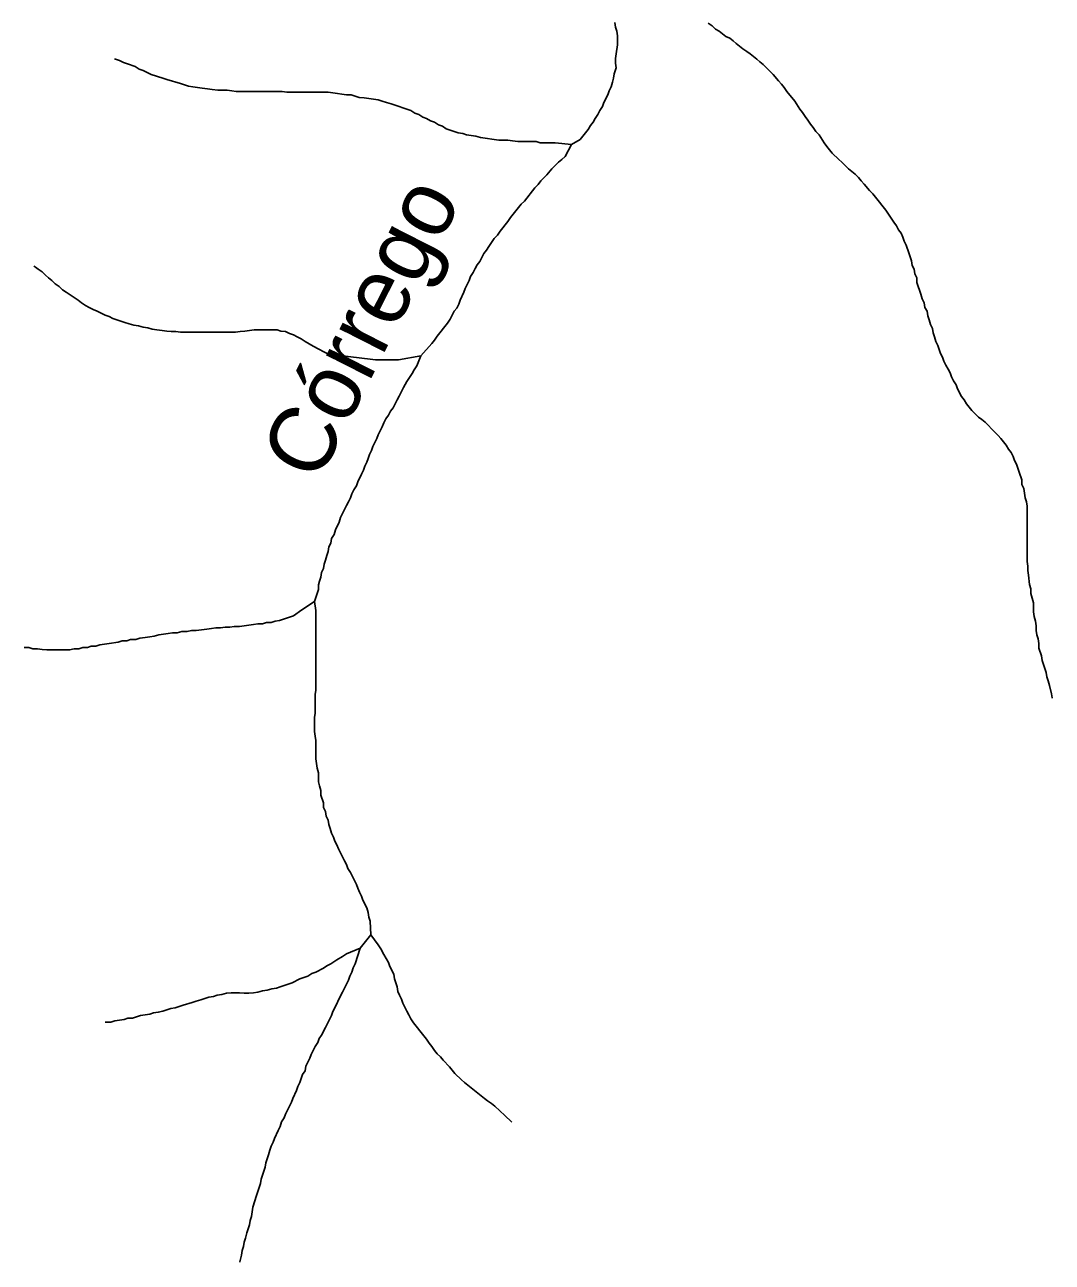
# Model space of a CAD drawing. Extents: x 652.3 to 678, y 7316.9 to 7344.9.
# Drawn here: x 674.888 to 676.134, y 7341.775 to 7343.275 of the extents above; entities that cross this region are included whole.
import ezdxf
from ezdxf.enums import TextEntityAlignment as Align

# ---------------------------------------------------------------- set-up
doc = ezdxf.new("R2010")
doc.units = 0
doc.header["$LTSCALE"] = 0.032
doc.layers.add('61', color=7, linetype='Continuous')
doc.layers.add('7', color=7, linetype='Continuous', lineweight=25)

msp = doc.modelspace()

# ---------------------------------------------------------------- linework, layer by layer
at = {"layer": '7'}
msp.add_line((675.3074, 7342.1721), (675.2947, 7342.1562), dxfattribs=at)
for points in [[(675.6034, 7343.2782), (675.6042, 7343.2726), (675.6058, 7343.2678), (675.6066, 7343.2622), (675.6066, 7343.2511), (675.605, 7343.24), (675.6042, 7343.2344), (675.6042, 7343.2288), (675.605, 7343.2233), (675.6026, 7343.2161), (675.6018, 7343.2105), (675.6003, 7343.2057), (675.5987, 7343.2002), (675.5963, 7343.1954), (675.5947, 7343.1906), (675.5899, 7343.1811), (675.5883, 7343.1763), (675.5851, 7343.1715), (675.5827, 7343.1668), (675.5796, 7343.162), (675.5772, 7343.1572), (675.574, 7343.1532), (675.5708, 7343.1485), (675.5644, 7343.1405), (675.5613, 7343.1365), (675.5509, 7343.1302)], [(675.7164, 7343.2774), (675.7212, 7343.2742), (675.7252, 7343.2702), (675.7299, 7343.2678), (675.7339, 7343.2646), (675.7379, 7343.2614), (675.7427, 7343.2591), (675.7467, 7343.2559), (675.7506, 7343.2527), (675.7546, 7343.2495), (675.7586, 7343.2463), (675.7634, 7343.2431), (675.7673, 7343.24), (675.7713, 7343.2368), (675.7753, 7343.2336), (675.7793, 7343.2304), (675.7833, 7343.2272), (675.7872, 7343.2233), (675.7912, 7343.2193), (675.7952, 7343.2153), (675.8016, 7343.2073), (675.8055, 7343.2034), (675.8087, 7343.1994), (675.8119, 7343.1946), (675.8215, 7343.1827), (675.8278, 7343.1731), (675.831, 7343.1691), (675.8342, 7343.1644), (675.8374, 7343.1596), (675.8405, 7343.1548), (675.8437, 7343.1508), (675.8469, 7343.1461), (675.8509, 7343.1421), (675.8573, 7343.1325), (675.8604, 7343.1278), (675.8636, 7343.1238), (675.8668, 7343.1198), (675.8748, 7343.1119), (675.8787, 7343.1087), (675.8827, 7343.1047), (675.8867, 7343.1007), (675.8907, 7343.0975), (675.8947, 7343.0944), (675.8986, 7343.0904), (675.9018, 7343.0864), (675.9058, 7343.0824), (675.9122, 7343.0745), (675.9161, 7343.0705), (675.9193, 7343.0665)], [(674.9965, 7343.2341), (675.0003, 7343.2328), (675.0027, 7343.232), (675.0075, 7343.2296), (675.0122, 7343.228), (675.0218, 7343.2248), (675.0266, 7343.2217), (675.0313, 7343.2201), (675.0409, 7343.2153), (675.0552, 7343.2105), (675.06, 7343.2089), (675.0767, 7343.2042), (675.0815, 7343.2026), (675.0862, 7343.201), (675.0918, 7343.2002), (675.0974, 7343.1994), (675.1029, 7343.1986), (675.1093, 7343.1978), (675.1149, 7343.197), (675.122, 7343.1962), (675.1332, 7343.1962), (675.1388, 7343.1954), (675.1443, 7343.1946), (675.2, 7343.1946), (675.2056, 7343.1938), (675.2557, 7343.1938), (675.2613, 7343.193), (675.2669, 7343.1922), (675.2724, 7343.1914), (675.278, 7343.1906), (675.2836, 7343.1906), (675.2883, 7343.189), (675.2931, 7343.1874), (675.2995, 7343.1867), (675.3051, 7343.1859), (675.3106, 7343.1851), (675.3162, 7343.1843), (675.321, 7343.1827), (675.3265, 7343.1811), (675.3321, 7343.1795), (675.3417, 7343.1763), (675.3464, 7343.1747), (675.356, 7343.1715), (675.3607, 7343.1684), (675.3655, 7343.1668), (675.3703, 7343.1636), (675.3751, 7343.162), (675.3798, 7343.1588), (675.3846, 7343.1572), (675.3894, 7343.154), (675.3942, 7343.1524), (675.3989, 7343.1493), (675.4133, 7343.1445), (675.4188, 7343.1437), (675.4236, 7343.1421), (675.4292, 7343.1413), (675.4347, 7343.1405), (675.4403, 7343.1389), (675.4459, 7343.1381), (675.457, 7343.1365), (675.4626, 7343.1357), (675.4737, 7343.1357), (675.4793, 7343.1349), (675.4857, 7343.1341), (675.508, 7343.1341), (675.5127, 7343.1325), (675.531, 7343.1325), (675.5509, 7343.1302)], [(675.5509, 7343.1302), (675.543, 7343.1158), (675.539, 7343.1119), (675.535, 7343.1087), (675.531, 7343.1047), (675.527, 7343.1007), (675.5207, 7343.0936), (675.5135, 7343.0864), (675.5103, 7343.0816), (675.5064, 7343.0776), (675.4936, 7343.0617), (675.4897, 7343.0578), (675.4865, 7343.0538), (675.4769, 7343.0418), (675.4737, 7343.0371), (675.4642, 7343.0251), (675.461, 7343.0204), (675.457, 7343.0164), (675.4538, 7343.0116), (675.4507, 7343.0068), (675.4475, 7343.0021), (675.4443, 7342.9981), (675.4395, 7342.9885), (675.4363, 7342.9845), (675.434, 7342.9798), (675.4316, 7342.975), (675.4284, 7342.9702), (675.4268, 7342.9655), (675.4244, 7342.9607), (675.422, 7342.9559), (675.4204, 7342.9511), (675.4157, 7342.9416), (675.4141, 7342.9368), (675.4117, 7342.932), (675.4085, 7342.9281), (675.4037, 7342.9185), (675.4005, 7342.9137), (675.3878, 7342.8978), (675.3846, 7342.893), (675.3814, 7342.8891), (675.3679, 7342.8739)], [(675.9193, 7343.0665), (675.9321, 7343.0506), (675.9384, 7343.041), (675.9416, 7343.0363), (675.9448, 7343.0315), (675.9472, 7343.0267), (675.9504, 7343.0227), (675.9527, 7343.018), (675.9543, 7343.0132), (675.9567, 7343.0084), (675.9599, 7342.9989), (675.9615, 7342.9941), (675.9631, 7342.9893), (675.9639, 7342.9838), (675.9663, 7342.979), (675.9671, 7342.9734), (675.9695, 7342.9686), (675.9695, 7342.9631), (675.971, 7342.9583), (675.9726, 7342.9535), (675.9742, 7342.9487), (675.9758, 7342.9432), (675.9782, 7342.9384), (675.979, 7342.9328), (675.9822, 7342.9281), (675.983, 7342.9225), (675.9846, 7342.9177), (675.9862, 7342.9121), (675.9885, 7342.9074), (675.9893, 7342.9018), (675.9909, 7342.897), (675.9925, 7342.8915), (675.9949, 7342.8867), (675.9965, 7342.8819), (675.9981, 7342.8771), (676.0005, 7342.8724), (676.0021, 7342.8676), (676.0045, 7342.8628), (676.0076, 7342.858), (676.01, 7342.8533), (676.0116, 7342.8485), (676.014, 7342.8437), (676.0172, 7342.8389), (676.0188, 7342.8342), (676.0236, 7342.8246), (676.0267, 7342.8206), (676.0299, 7342.8159), (676.0331, 7342.8119), (676.0363, 7342.8079), (676.0442, 7342.7999), (676.0482, 7342.7968), (676.0522, 7342.7936), (676.0562, 7342.7896), (676.0602, 7342.7856), (676.0641, 7342.7816), (676.0681, 7342.7777), (676.0713, 7342.7737), (676.0777, 7342.7657), (676.0808, 7342.761), (676.084, 7342.757), (676.0864, 7342.7522), (676.088, 7342.7474), (676.0904, 7342.7427), (676.092, 7342.7379), (676.0936, 7342.7331), (676.0968, 7342.7236), (676.0968, 7342.718), (676.0991, 7342.7132), (676.0999, 7342.7076), (676.1007, 7342.7021), (676.1023, 7342.6973), (676.1031, 7342.6917), (676.1031, 7342.6249), (676.1039, 7342.6193), (676.1039, 7342.6138), (676.1047, 7342.6082), (676.1063, 7342.597), (676.1079, 7342.5915), (676.1079, 7342.5859), (676.1095, 7342.5803), (676.1111, 7342.5748), (676.1111, 7342.5636), (676.1119, 7342.5581), (676.1135, 7342.5525), (676.1143, 7342.5469), (676.1143, 7342.5413), (676.1151, 7342.5358), (676.1167, 7342.531), (676.1174, 7342.5254), (676.1174, 7342.5199), (676.1206, 7342.5103), (676.1214, 7342.5047), (676.123, 7342.5), (676.1246, 7342.4952), (676.1262, 7342.4904), (676.127, 7342.4849), (676.1286, 7342.4801), (676.1302, 7342.4745), (676.1326, 7342.4642), (676.1336, 7342.4595), (676.1337, 7342.4591)], [(674.8989, 7342.9828), (674.8996, 7342.9823), (674.9008, 7342.9814), (674.904, 7342.979), (674.9088, 7342.9758), (674.9128, 7342.9718), (674.9168, 7342.9686), (674.9207, 7342.9655), (674.9247, 7342.9615), (674.9295, 7342.9583), (674.9335, 7342.9543), (674.9382, 7342.9511), (674.943, 7342.9479), (674.9478, 7342.9448), (674.9526, 7342.9416), (674.9565, 7342.9384), (674.9613, 7342.9352), (674.9661, 7342.9328), (674.9709, 7342.9304), (674.9756, 7342.9281), (674.9804, 7342.9257), (674.9852, 7342.9233), (674.99, 7342.9217), (674.9947, 7342.9193), (674.9995, 7342.9177), (675.0043, 7342.9161), (675.0091, 7342.9145), (675.0146, 7342.9129), (675.0202, 7342.9113), (675.0258, 7342.9105), (675.0313, 7342.909), (675.0369, 7342.9082), (675.0425, 7342.9066), (675.048, 7342.9058), (675.0544, 7342.905), (675.06, 7342.9042), (675.0655, 7342.9034), (675.0711, 7342.9034), (675.0767, 7342.9026), (675.0823, 7342.9026), (675.0878, 7342.9026), (675.0934, 7342.9026), (675.099, 7342.9026), (675.1045, 7342.9026), (675.1101, 7342.9026), (675.1157, 7342.9026), (675.1212, 7342.9026), (675.1268, 7342.9026), (675.1324, 7342.9026), (675.138, 7342.9026), (675.1435, 7342.9026), (675.1491, 7342.9034), (675.1547, 7342.9042), (675.1602, 7342.905), (675.1658, 7342.9058), (675.1714, 7342.9058), (675.1769, 7342.9058), (675.1825, 7342.9058), (675.1881, 7342.9058), (675.1937, 7342.9058), (675.1984, 7342.9042), (675.204, 7342.9034), (675.2088, 7342.901), (675.2135, 7342.8994), (675.2183, 7342.897), (675.2231, 7342.8946), (675.2279, 7342.8915), (675.2374, 7342.8859), (675.2573, 7342.8755), (675.2565, 7342.8763), (675.3066, 7342.87), (675.313, 7342.8692), (675.3409, 7342.8692), (675.3679, 7342.8739)], [(675.3679, 7342.8739), (675.3631, 7342.862), (675.36, 7342.8572), (675.3576, 7342.8525), (675.3544, 7342.8477), (675.3512, 7342.8429), (675.3472, 7342.8358), (675.3417, 7342.8254), (675.3393, 7342.8206), (675.3369, 7342.8159), (675.3345, 7342.8111), (675.3313, 7342.8071), (675.3289, 7342.8023), (675.3257, 7342.7976), (675.3234, 7342.7928), (675.321, 7342.788), (675.3162, 7342.7785), (675.3146, 7342.7737), (675.3122, 7342.7689), (675.3098, 7342.7641), (675.3082, 7342.7594), (675.3058, 7342.7546), (675.3043, 7342.7498), (675.3027, 7342.745), (675.3003, 7342.7403), (675.2987, 7342.7355), (675.2963, 7342.7307), (675.2915, 7342.7212), (675.2899, 7342.7164), (675.2867, 7342.7116), (675.2844, 7342.7069), (675.2828, 7342.7021), (675.2804, 7342.6973), (675.278, 7342.6925), (675.2708, 7342.6782), (675.2692, 7342.6726), (675.2645, 7342.6631), (675.2629, 7342.6575), (675.2597, 7342.6527), (675.2589, 7342.6472), (675.2565, 7342.6424), (675.2557, 7342.6368), (675.2541, 7342.6321), (675.2525, 7342.6265), (675.2509, 7342.6217), (675.2501, 7342.6161), (675.2478, 7342.6114), (675.247, 7342.6058), (675.2454, 7342.601), (675.2438, 7342.5963), (675.2438, 7342.5907), (675.239, 7342.5764)], [(674.8873, 7342.5207), (674.8929, 7342.5207), (674.8977, 7342.5191), (674.9032, 7342.5191), (674.9088, 7342.5183), (674.9144, 7342.5175), (674.9422, 7342.5175), (674.9478, 7342.5191), (674.9534, 7342.5191), (674.9581, 7342.5207), (674.9637, 7342.5207), (674.9685, 7342.5223), (674.974, 7342.5223), (674.9788, 7342.5238), (674.9844, 7342.5246), (674.99, 7342.5254), (675.0011, 7342.527), (675.0059, 7342.5286), (675.0114, 7342.5286), (675.0162, 7342.5302), (675.0226, 7342.5302), (675.0274, 7342.5318), (675.0337, 7342.5326), (675.0393, 7342.5334), (675.0449, 7342.5342), (675.0504, 7342.5358), (675.0616, 7342.5374), (675.0671, 7342.5382), (675.0727, 7342.5382), (675.0783, 7342.5398), (675.0846, 7342.5398), (675.0902, 7342.5413), (675.0958, 7342.5413), (675.1021, 7342.5421), (675.1085, 7342.5429), (675.1141, 7342.5437), (675.1197, 7342.5445), (675.1252, 7342.5445), (675.1308, 7342.5453), (675.1364, 7342.5453), (675.1419, 7342.5461), (675.1483, 7342.5461), (675.1539, 7342.5469), (675.1594, 7342.5477), (675.165, 7342.5485), (675.1706, 7342.5493), (675.1761, 7342.5493), (675.1809, 7342.5509), (675.1865, 7342.5509), (675.1913, 7342.5525), (675.1968, 7342.5533), (675.2016, 7342.5549), (675.2064, 7342.5565), (675.2135, 7342.5589), (675.2239, 7342.566), (675.239, 7342.5764)], [(675.239, 7342.5764), (675.2406, 7342.5652), (675.2406, 7342.4689), (675.2398, 7342.4634), (675.2398, 7342.4411), (675.239, 7342.4355), (675.239, 7342.4188), (675.2398, 7342.4132), (675.2406, 7342.4077), (675.2406, 7342.3854), (675.2422, 7342.3743), (675.2438, 7342.3687), (675.2438, 7342.3575), (675.2454, 7342.3528), (675.247, 7342.3472), (675.247, 7342.3416), (675.2501, 7342.3321), (675.2501, 7342.3265), (675.2525, 7342.3217), (675.2533, 7342.3162), (675.2557, 7342.3114), (675.2565, 7342.3058), (675.2581, 7342.3011), (675.2597, 7342.2955), (675.2621, 7342.2907), (675.2637, 7342.2859), (675.2661, 7342.2812), (675.2684, 7342.2764), (675.2756, 7342.2621), (675.278, 7342.2573), (675.2796, 7342.2525), (675.2828, 7342.2477), (675.2852, 7342.243), (675.2875, 7342.2382), (675.2899, 7342.2334), (675.2915, 7342.2286), (675.2939, 7342.2239), (675.2963, 7342.2191), (675.2979, 7342.2143), (675.3027, 7342.2048), (675.3043, 7342.1992), (675.3051, 7342.1936), (675.3066, 7342.1889), (675.3074, 7342.1721)], [(675.3074, 7342.1721), (675.3162, 7342.1602), (675.3194, 7342.1554), (675.3234, 7342.1483), (675.3289, 7342.1387), (675.3305, 7342.134), (675.3353, 7342.1244), (675.3361, 7342.1188), (675.3393, 7342.1093), (675.3401, 7342.1037), (675.3424, 7342.0989), (675.3448, 7342.0942), (675.3464, 7342.0894), (675.3512, 7342.0798), (675.3536, 7342.0751), (675.356, 7342.0703), (675.3592, 7342.0655), (675.3719, 7342.0496), (675.3751, 7342.0456), (675.3783, 7342.0409), (675.3814, 7342.0369), (675.3846, 7342.0321), (675.3878, 7342.0281), (675.3918, 7342.0242), (675.395, 7342.0202), (675.4029, 7342.0122), (675.4093, 7342.0043), (675.4172, 7341.9963), (675.4212, 7341.9931), (675.4252, 7341.9899), (675.4292, 7341.9868), (675.4332, 7341.9836), (675.4371, 7341.9804), (675.4411, 7341.9772), (675.4451, 7341.974), (675.4491, 7341.9708), (675.4538, 7341.9677), (675.4578, 7341.9645), (675.4698, 7341.9533), (675.4779, 7341.9457), (675.4785, 7341.9452)], [(674.9852, 7342.0663), (674.9923, 7342.0663), (674.9971, 7342.0679), (675.0027, 7342.0687), (675.0083, 7342.0695), (675.013, 7342.0711), (675.0186, 7342.0711), (675.0234, 7342.0727), (675.0282, 7342.0743), (675.0337, 7342.0751), (675.0393, 7342.0759), (675.0441, 7342.0775), (675.0496, 7342.0783), (675.0552, 7342.0798), (675.06, 7342.0814), (675.0648, 7342.083), (675.0703, 7342.0838), (675.0751, 7342.0854), (675.0799, 7342.087), (675.091, 7342.0902), (675.0958, 7342.0918), (675.1014, 7342.0934), (675.1109, 7342.0966), (675.1165, 7342.0974), (675.1212, 7342.0989), (675.1268, 7342.0997), (675.1324, 7342.1013), (675.138, 7342.1021), (675.1483, 7342.1021), (675.1539, 7342.1013), (675.1594, 7342.1013), (675.165, 7342.1021), (675.1706, 7342.1029), (675.1761, 7342.1045), (675.1817, 7342.1053), (675.1873, 7342.1069), (675.1929, 7342.1077), (675.1976, 7342.1093), (675.2024, 7342.1109), (675.212, 7342.1141), (675.2215, 7342.1188), (675.2311, 7342.122), (675.2358, 7342.1252), (675.2406, 7342.1268), (675.2501, 7342.1316), (675.2541, 7342.1348), (675.2589, 7342.1371), (675.2661, 7342.1419), (675.2732, 7342.1459), (675.278, 7342.1491), (675.2947, 7342.1562)], [(675.1485, 7341.7753), (675.1487, 7341.776), (675.1499, 7341.7807), (675.1507, 7341.7839), (675.1515, 7341.7894), (675.1531, 7341.7942), (675.1539, 7341.7998), (675.1555, 7341.8045), (675.1571, 7341.8109), (675.1602, 7341.8205), (675.161, 7341.826), (675.1626, 7341.8308), (675.1642, 7341.8419), (675.169, 7341.8563), (675.1706, 7341.861), (675.1738, 7341.8706), (675.1746, 7341.8762), (675.1793, 7341.8905), (675.1801, 7341.896), (675.1817, 7341.9008), (675.1833, 7341.9056), (675.1849, 7341.9112), (675.1865, 7341.9159), (675.1889, 7341.9207), (675.1905, 7341.9255), (675.1952, 7341.935), (675.1976, 7341.9398), (675.1992, 7341.9454), (675.2024, 7341.9502), (675.204, 7341.9549), (675.2088, 7341.9645), (675.2112, 7341.9692), (675.2128, 7341.974), (675.2175, 7341.9836), (675.2191, 7341.9883), (675.2215, 7341.9931), (675.2247, 7342.0027), (675.2279, 7342.0074), (675.2287, 7342.013), (675.2311, 7342.0178), (675.2334, 7342.0226), (675.235, 7342.0273), (675.2398, 7342.0369), (675.243, 7342.0417), (675.2446, 7342.0464), (675.2478, 7342.0504), (675.2525, 7342.06), (675.2549, 7342.0647), (675.2597, 7342.0743), (675.2613, 7342.0791), (675.2637, 7342.0838), (675.2708, 7342.0982), (675.2732, 7342.1029), (675.2804, 7342.1172), (675.282, 7342.122), (675.2844, 7342.1268), (675.286, 7342.1324), (675.2883, 7342.1371), (675.2947, 7342.1562)]]:
    msp.add_lwpolyline(points, dxfattribs=at)

# ---------------------------------------------------------------- texts
at = {"layer": '61'}
msp.add_text('Córrego', height=0.08, rotation=63.043, dxfattribs=at).set_placement((675.3303, 7342.8907), align=Align.CENTER)

doc.saveas('drawing.dxf')
